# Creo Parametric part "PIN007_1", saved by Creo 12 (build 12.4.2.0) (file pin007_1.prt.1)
Units: Custom; MM, KILOGRAM, SECS

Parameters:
  PTC_WM_ITERATION = "0"
  PTC_WM_VERSION = "-.0"
  PTC_WM_LIFECYCLE_STATE = "In Work"
  PTC_WM_LIFECYCLE = "MO_CADDocument"
  PTC_WM_CREATED_BY = "Maximilian Roepper (Z0017RMS: MO)"
  PTC_WM_CREATED_ON = "18-Sep-26 11:36:42 AM"
  PTC_WM_MODIFIED_BY = "Maximilian Roepper (Z0017RMS: MO)"
  PTC_WM_MODIFIED_ON = "18-Sep-26 11:36:46 AM"
  PDMLINKNUMBER = "PDM000071454973"
  PTC_WM_NAME = "pin007_1.prt"
  PTC_WM_NUMBER = "PDM000071454973"

Other parameters: WEIGHT, WEIGHT_FACTOR, WEIGHT_ADD, _MASS_TEMP, _DIFF_TEMP, MC_ERRORS, SUPPLIER

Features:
  1. coordinate system
  2. datum plane "PRT_YZ"
  3. datum plane "PRT_XY"
  4. datum plane "PRT_XZ"
  5. coordinate system
  6. datum axis
  7. datum axis
  8. datum axis
  9. coordinate system
  10. imported feature

Other named items: PRT, SIEMENS_MO, DRW_VIEW_ORG, PRT_X, PRT_Y, PRT_Z, CS0, ROUGH_GROB

Layers: 00_STD_CSYS-KSYS, 01_STD_PLANES-EBENEN, 02_STD_AXES-ACHSEN, 03_STD_CSYS-KSYS, 24_IMPORT_FEAT-IMPORT_KE

Surfaces: 14 plane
